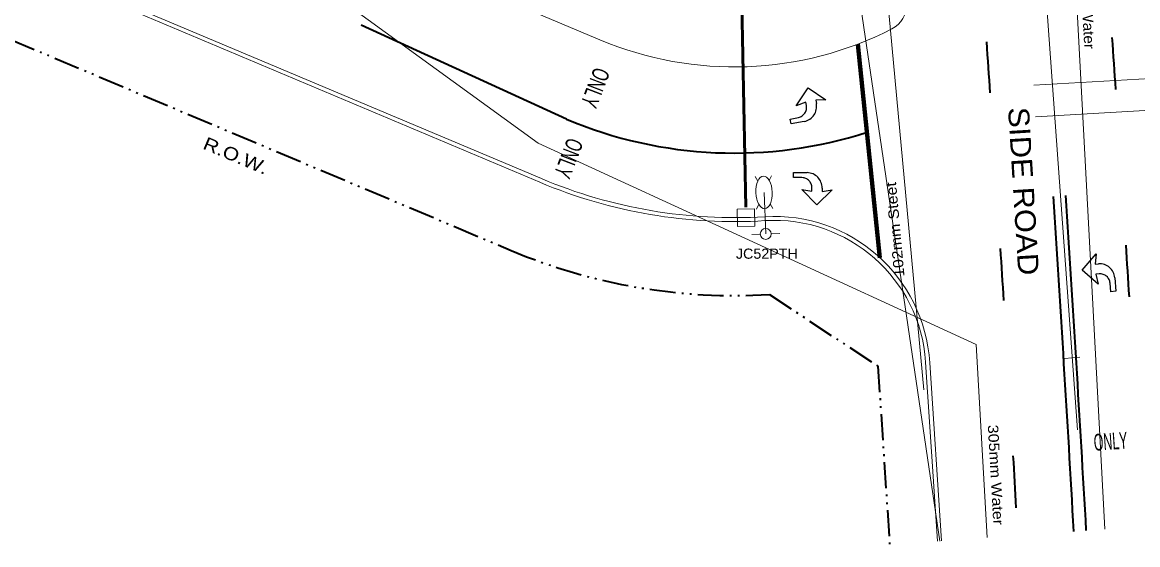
# Model space of a CAD drawing. Extents: x 168203 to 169863, y 223196 to 223870.
# Drawn here: x 168295 to 168359.5, y 223553.2 to 223583.4 of the extents above; entities that cross this region are included whole.
import ezdxf
from ezdxf.enums import TextEntityAlignment as Align

# ---------------------------------------------------------------- set-up
doc = ezdxf.new("R2010")
doc.units = 0
doc.header["$LTSCALE"] = 0.3
doc.linetypes.add('DASH_DOUBLE_DOT', pattern=[9.2, 5, -1.2, 0.3, -1.2, 0.3, -1.2])
doc.linetypes.add('LONG_DASH_SHORT_DASH', pattern=[9.9, 6, -1.2, 1.5, -1.2])
for name, color, linetype, lineweight in [('1', 7, 'Continuous', 13), ('23', 7, 'Continuous', 25), ('36', 7, 'Continuous', 35)]:
    doc.layers.add(name, color=color, linetype=linetype, lineweight=lineweight)

msp = doc.modelspace()

# ---------------------------------------------------------------- linework, layer by layer
at = {"layer": '1'}
for p, q in [((168355.9956, 223559.8648), (168350.6186, 223634.2675)), ((168237.0809, 223611.1663), (168324.9428, 223574.1566)), ((168237.1701, 223611.3783), (168325.032, 223574.3686)), ((168280.5516, 223602.5453), (168328.4093, 223582.3863)), ((168337.5271, 223574.2165), (168337.3804, 223574.4911)), ((168338.1945, 223574.2615), (168338.3194, 223574.5288)), ((168337.9914, 223571.1736), (168337.8949, 223573.5716)), ((168337.5896, 223572.8897), (168337.456, 223572.613)), ((168338.2486, 223572.9162), (168338.3949, 223572.6508)), ((168337.6792, 223571.161), (168337.1796, 223571.1409)), ((168338.3036, 223571.1862), (168338.8032, 223571.2063)), ((168355.2465, 223563.9874), (168356.1442, 223564.0523)), ((168347.2313, 223563.7792), (168347.914, 223553.4338)), ((168347.4644, 223563.7395), (168348.1434, 223553.4503))]:
    msp.add_line(p, q, dxfattribs=at)
at = {"layer": '1', "linetype": 'DASH_DOUBLE_DOT', "lineweight": 35}
msp.add_line((168235.4238, 223607.2309), (168323.2857, 223570.2212), dxfattribs=at)
at = {"layer": '1'}
msp.add_lwpolyline([(168336.3628, 223571.597), (168336.3426, 223572.5998), (168337.3454, 223572.62), (168337.3656, 223571.6172)], close=True, dxfattribs=at)
at = {"layer": '1', "linetype": 'DASH_DOUBLE_DOT', "lineweight": 35}
msp.add_lwpolyline([(168338.2062, 223567.6799), (168344.4714, 223563.5417), (168345.1516, 223553.2343)], dxfattribs=at)
at = {"layer": '1'}
msp.add_circle((168337.9914, 223571.1736), 0.3125, dxfattribs=at)
for centre, radius, start, end in [((168344.6012, 223584.3492), 1.5, 297.10142, 4.13349), ((168336.1731, 223600.8178), 20, 247.15789, 297.10142), ((168336.1731, 223600.8178), 28.7, 247.15789, 273.50996), ((168336.1731, 223600.8178), 28.93, 247.15789, 273.50996), ((168338.4812, 223563.1885), 9, 3.50996, 93.50996), ((168338.4812, 223563.1885), 8.77, 3.86221, 93.50996)]:
    msp.add_arc(centre, radius, start, end, dxfattribs=at)
at = {"layer": '1', "linetype": 'DASH_DOUBLE_DOT', "lineweight": 35}
msp.add_arc((168336.1737, 223600.8176), 33.2, 247.15789, 273.50996, dxfattribs=at)
at = {"layer": '1'}
msp.add_ellipse((168337.8949, 223573.5716), major_axis=(0.0378, -0.9405), ratio=0.504, dxfattribs=at)
at = {"layer": '23', "lineweight": 13}
for p, q in [((168357.586, 223554.132), (168349.5897, 223703.4835)), ((168347.1263, 223562.1814), (168341.4609, 223622.959)), ((168348.0491, 223553.4435), (168338.6279, 223617.1375)), ((168353.4742, 223579.7703), (168397.1161, 223582.2547)), ((168353.5788, 223577.9352), (168363.5377, 223578.5022)), ((168350.7807, 223553.6407), (168350.1491, 223564.7839))]:
    msp.add_line(p, q, dxfattribs=at)
at = {"layer": '23', "lineweight": 53}
msp.add_line((168336.8416, 223572.7261), (168336.6026, 223584.4228), dxfattribs=at)
at = {"layer": '23', "lineweight": 13}
msp.add_lwpolyline([(168266.2242, 223619.4347), (168285.4048, 223610.1272), (168313.047, 223584.9747), (168324.8486, 223576.4143), (168350.1491, 223564.7839)], dxfattribs=at)
at = {"layer": '36'}
msp.add_line((168326.4792, 223577.8024), (168314.608, 223583.2371), dxfattribs=at)
at = {"layer": '36', "lineweight": 80}
msp.add_line((168343.3205, 223582.1379), (168344.5892, 223569.7987), dxfattribs=at)
at = {"layer": '36', "linetype": 'LONG_DASH_SHORT_DASH', "lineweight": 25}
for points in [[(168340.3403, 223578.5896), (168340.3031, 223578.7811), (168339.7473, 223578.5738), (168340.4415, 223579.6029), (168341.4706, 223578.9087), (168340.8776, 223578.8927), (168340.9148, 223578.7012)], [(168340.2206, 223577.6721), (168339.4546, 223577.5232), (168339.3988, 223577.8105), (168339.8775, 223577.9035)], [(168340.0847, 223574.4257), (168339.597, 223574.4335), (168339.6017, 223574.726), (168340.3819, 223574.7136)], [(168341.2456, 223573.822), (168341.2425, 223573.627), (168341.8292, 223573.7152), (168340.9376, 223572.8514), (168340.0738, 223573.743), (168340.6574, 223573.6362), (168340.6605, 223573.8313)], [(168357.2621, 223568.8694), (168357.0675, 223568.8553), (168357.2069, 223568.2787), (168356.2681, 223569.0909), (168357.0803, 223570.0297), (168357.0253, 223569.439), (168357.2199, 223569.4531)], [(168358.1587, 223568.6408), (168358.2149, 223567.8626), (168357.9231, 223567.8415), (168357.8879, 223568.3279)]]:
    msp.add_lwpolyline(points, dxfattribs=at)
at = {"layer": '36'}
for centre, radius, start, end in [((166159.6765, 223429.5465), 2196.4, 3.90994, 3.98699), ((166159.6765, 223429.5465), 2203.6498, 3.90229, 3.98029), ((168336.1737, 223600.8174), 24.9735, 247.15789, 287.88562), ((166159.6765, 223429.5465), 2199.64, 3.24354, 3.74834), ((166159.6765, 223429.5465), 2200.36, 3.24383, 3.74834), ((166159.6765, 223429.5465), 2196.4, 3.59691, 3.67517), ((166159.6765, 223429.5465), 2203.6498, 3.59029, 3.66829), ((166159.6765, 223429.5465), 2196.4, 3.28387, 3.36213)]:
    msp.add_arc(centre, radius, start, end, dxfattribs=at)
at = {"layer": '36', "linetype": 'LONG_DASH_SHORT_DASH', "lineweight": 25}
for centre, radius, start, end in [((168340.0531, 223578.5338), 0.8778, 280.99748, 10.99748), ((168339.7659, 223578.478), 0.5852, 280.99748, 10.99748), ((168340.0753, 223573.8406), 0.5852, 359.09119, 89.09119), ((168340.3679, 223573.8359), 0.8778, 359.09119, 89.09119), ((168357.2831, 223568.5775), 0.8778, 4.13419, 94.13419), ((168357.3042, 223568.2857), 0.5852, 4.13419, 94.13419)]:
    msp.add_arc(centre, radius, start, end, dxfattribs=at)

# ---------------------------------------------------------------- texts
at = {"layer": '1'}
for s, height, rotation, width, p in [('SIDE ROAD', 1.202, 273.525, 1.1, (168352.2895, 223573.6061)), ('R.O.W.', 0.7499, 337.158, 1.2, (168307.2321, 223575.3468))]:
    msp.add_text(s, height=height, rotation=rotation, dxfattribs=dict(at, width=width)).set_placement(p, align=Align.CENTER)
at = {"layer": '1', "width": 1.05}
msp.add_text('JC52PTH', height=0.5873, dxfattribs=at).set_placement((168338.0555, 223569.7421), align=Align.CENTER)
at = {"layer": '23'}
for s, rotation, width, p in [('152mm Water', 273.065, 1.1, (168356.2546, 223584.6096)), ('102mm Steet', 95.197, 1.15, (168345.763, 223571.4549)), ('305mm Water', 273.244, 1.15, (168350.9822, 223557.2471))]:
    msp.add_text(s, height=0.6, rotation=rotation, dxfattribs=dict(at, width=width)).set_placement(p, align=Align.CENTER)
at = {"layer": '36'}
for rotation, width, p in [(249.03, 0.65, (168327.6914, 223579.7877)), (249.03, 0.65, (168326.1512, 223575.7195)), (3.898, 0.55, (168357.9473, 223558.7163))]:
    msp.add_text('ONLY', height=0.9715, rotation=rotation, dxfattribs=dict(at, width=width)).set_placement(p, align=Align.CENTER)

doc.saveas('drawing.dxf')
